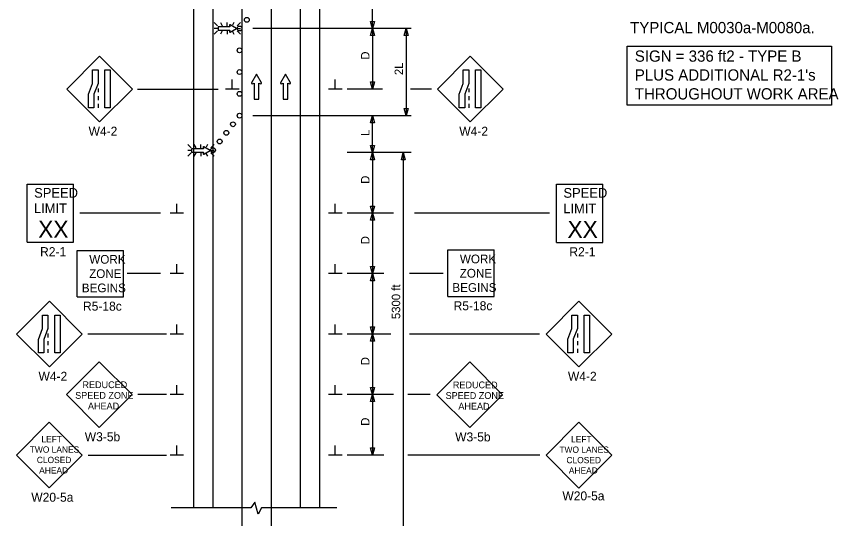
# Model space of a CAD drawing. Extents: x 16553 to 18478, y 5759 to 7026.
# Drawn here: x 16725 to 17405, y 6259 to 6674 of the extents above; entities that cross this region are included whole.
import ezdxf

# ---------------------------------------------------------------- set-up
doc = ezdxf.new("R2010")
doc.units = 0
for name, color, linetype in [('ALI_LEGAL_EX', 7, 'Continuous'), ('MT_SCRATCH_LEVEL_E', 7, 'Continuous'), ('PAVT_EDGE_EX', 7, 'Continuous'), ('TRAFFIC_SIGNS_PR', 7, 'Continuous'), ('TYPICAL_TEXT_DIMEN_EX', 7, 'Continuous'), ('TYPICAL_TEXT_DIMEN_PR', 7, 'Continuous')]:
    doc.layers.add(name, color=color, linetype=linetype)

msp = doc.modelspace()

# ---------------------------------------------------------------- linework, layer by layer
at = {"layer": 'ALI_LEGAL_EX'}
for p, q in [((16911.66, 7026.35), (16911.66, 6197.16)), ((16935.66, 7026.35), (16935.66, 6197.16)), ((16935.66, 7026.35), (16935.66, 6197.16))]:
    msp.add_line(p, q, dxfattribs=at)
for points in [[(16911.66, 6626.35), (16911.66, 6601.35)], [(16935.66, 6626.35), (16935.66, 6601.35)], [(16911.66, 6526.35), (16911.66, 6501.35)], [(16935.66, 6526.35), (16935.66, 6501.35)], [(16911.66, 6426.35), (16911.66, 6401.35)], [(16935.66, 6426.35), (16935.66, 6401.35)], [(16911.66, 6326.35), (16911.66, 6301.35)], [(16935.66, 6326.35), (16935.66, 6301.35)]]:
    msp.add_lwpolyline(points, dxfattribs=at)
at = {"layer": 'MT_SCRATCH_LEVEL_E'}
for p, q in [((16923.57, 6625.97), (16919.46, 6618.73)), ((16927.71, 6618.73), (16923.57, 6625.97)), ((16947.62, 6625.97), (16943.51, 6618.73)), ((16951.77, 6618.73), (16947.62, 6625.97)), ((16919.94, 6618.04), (16921.72, 6618.36)), ((16921.72, 6618.36), (16921.72, 6605.1)), ((16925.46, 6605.1), (16925.46, 6618.36)), ((16925.46, 6618.36), (16927.23, 6618.04)), ((16943.99, 6618.04), (16945.77, 6618.36)), ((16945.77, 6618.36), (16945.77, 6605.1)), ((16949.51, 6605.1), (16949.51, 6618.36)), ((16949.51, 6618.36), (16951.29, 6618.04)), ((16921.72, 6605.1), (16925.46, 6605.1)), ((16945.77, 6605.1), (16949.51, 6605.1))]:
    msp.add_line(p, q, dxfattribs=at)
for centre, start, end in [((16919.86, 6618.5), 150.42484, 279.96381), ((16927.3, 6618.5), 260.03619, 29.77312), ((16943.92, 6618.5), 150.42484, 279.96381), ((16951.36, 6618.5), 260.03619, 29.77312)]:
    msp.add_arc(centre, 0.463, start, end, dxfattribs=at)
at = {"layer": 'PAVT_EDGE_EX'}
for p, q in [((16871.66, 6926.66), (16871.66, 6267.34)), ((16887.66, 6926.66), (16887.66, 6267.34)), ((16959.66, 6926.66), (16959.66, 6267.34)), ((16975.66, 6926.66), (16975.66, 6267.34))]:
    msp.add_line(p, q, dxfattribs=at)
at = {"layer": 'TRAFFIC_SIGNS_PR'}
for p, q in [((16891.44, 6665.74), (16888.62, 6668.56)), ((16893.74, 6668.56), (16895.36, 6665.74)), ((16899.52, 6665.74), (16899.52, 6668.56)), ((16904.99, 6668.56), (16903.79, 6666.46)), ((16910.43, 6668.55), (16907.61, 6665.74)), ((16891.44, 6663.7), (16888.62, 6663.7)), ((16891.44, 6661.67), (16888.62, 6658.85)), ((16895.39, 6661.67), (16893.76, 6658.85)), ((16899.52, 6661.67), (16899.52, 6658.85)), ((16903.71, 6661.04), (16904.97, 6658.85)), ((16907.61, 6663.7), (16910.43, 6663.7)), ((16910.43, 6658.85), (16907.61, 6661.67)), ((16793.8, 6640.77), (16766.64, 6613.62)), ((16820.95, 6613.62), (16793.8, 6640.77)), ((17100.48, 6640.77), (17073.32, 6613.62)), ((17127.63, 6613.62), (17100.48, 6640.77)), ((16766.64, 6613.62), (16793.8, 6586.47)), ((16792.55, 6614.11), (16792.55, 6610.91)), ((16793.8, 6586.47), (16820.95, 6613.62)), ((17073.32, 6613.62), (17100.48, 6586.46)), ((17099.23, 6614.11), (17099.23, 6610.91)), ((17100.48, 6586.46), (17127.63, 6613.62)), ((16792.55, 6607.71), (16792.55, 6604.51)), ((17099.23, 6607.71), (17099.23, 6604.51)), ((16792.55, 6601.31), (16792.55, 6598.11)), ((17099.23, 6601.31), (17099.23, 6598.11)), ((16869.6, 6564.95), (16866.78, 6567.77)), ((16871.9, 6567.77), (16873.52, 6564.95)), ((16877.68, 6564.95), (16877.68, 6567.77)), ((16883.15, 6567.77), (16881.94, 6565.68)), ((16888.59, 6567.77), (16885.77, 6564.95)), ((16869.6, 6562.92), (16866.78, 6562.92)), ((16869.6, 6560.88), (16866.78, 6558.06)), ((16873.55, 6560.88), (16871.92, 6558.06)), ((16877.68, 6560.88), (16877.68, 6558.06)), ((16881.87, 6560.25), (16883.13, 6558.06)), ((16885.77, 6562.92), (16888.59, 6562.92)), ((16888.59, 6558.07), (16885.77, 6560.88)), ((16733.92, 6534.98), (16772.37, 6534.98)), ((16733.92, 6486.92), (16733.92, 6534.98)), ((16772.37, 6486.92), (16772.37, 6534.98)), ((17171.81, 6534.92), (17210.26, 6534.92)), ((17171.81, 6486.86), (17171.81, 6534.92)), ((17210.26, 6486.86), (17210.26, 6534.92)), ((16733.92, 6486.92), (16772.37, 6486.92)), ((17171.81, 6486.86), (17210.26, 6486.86)), ((16775.32, 6441.85), (16775.32, 6480.25)), ((16775.32, 6480.25), (16813.72, 6480.25)), ((16813.72, 6441.85), (16813.72, 6480.25)), ((17081.91, 6442.19), (17081.91, 6480.59)), ((17081.91, 6480.59), (17120.31, 6480.59)), ((17120.31, 6442.19), (17120.31, 6480.59)), ((16775.32, 6441.85), (16813.72, 6441.85)), ((17081.91, 6442.19), (17120.31, 6442.19)), ((16752.35, 6438.19), (16725.19, 6411.04)), ((16779.5, 6411.04), (16752.35, 6438.19)), ((17190.35, 6438.22), (17163.2, 6411.06)), ((17217.51, 6411.06), (17190.35, 6438.22)), ((16725.19, 6411.04), (16752.35, 6383.89)), ((16751.1, 6411.53), (16751.1, 6408.33)), ((16752.35, 6383.89), (16779.5, 6411.04)), ((17163.2, 6411.06), (17190.35, 6383.91)), ((17189.11, 6411.55), (17189.11, 6408.35)), ((17190.35, 6383.91), (17217.51, 6411.06)), ((16751.1, 6405.13), (16751.1, 6401.93)), ((17189.11, 6405.15), (17189.11, 6401.95)), ((16751.1, 6398.73), (16751.1, 6395.53)), ((17189.11, 6398.75), (17189.11, 6395.55)), ((16793.62, 6388.23), (16766.47, 6361.08)), ((16820.78, 6361.08), (16793.62, 6388.23)), ((17100.06, 6388.12), (17072.91, 6360.97)), ((17127.21, 6360.97), (17100.06, 6388.12)), ((16766.47, 6361.08), (16793.62, 6333.93)), ((16793.62, 6333.93), (16820.78, 6361.08)), ((17072.91, 6360.97), (17100.06, 6333.81)), ((17100.06, 6333.81), (17127.21, 6360.97)), ((16752.21, 6338.25), (16725.06, 6311.09)), ((16779.37, 6311.09), (16752.21, 6338.25)), ((17190.37, 6338.15), (17163.22, 6310.99)), ((17217.52, 6310.99), (17190.37, 6338.15)), ((16725.06, 6311.09), (16752.21, 6283.94)), ((16752.21, 6283.94), (16779.37, 6311.09)), ((17163.22, 6310.99), (17190.37, 6283.84)), ((17190.37, 6283.84), (17217.52, 6310.99))]:
    msp.add_line(p, q, dxfattribs=at)
for points in [[(16901.35, 6666.39), (16901.58, 6665.09), (16891.86, 6665.09), (16891.86, 6662.35), (16901.58, 6662.35), (16901.35, 6661.04)], [(16901.85, 6660.69), (16907.16, 6663.7), (16901.85, 6666.74)], [(16879.51, 6565.6), (16879.74, 6564.3), (16870.02, 6564.3), (16870.02, 6561.56), (16879.74, 6561.56), (16879.51, 6560.26)], [(16880.01, 6559.9), (16885.32, 6562.92), (16880.01, 6565.96)]]:
    msp.add_lwpolyline(points, dxfattribs=at)
for points in [[(16792.55, 6629.36), (16792.55, 6618.18), (16789.2, 6609.29), (16789.2, 6598.11), (16784.71, 6598.11), (16784.71, 6609.29), (16788.05, 6618.18), (16788.05, 6629.36)], [(16802.68, 6629.36), (16802.68, 6598.11), (16798.19, 6598.11), (16798.19, 6629.36)], [(17099.23, 6629.35), (17099.23, 6618.17), (17095.88, 6609.29), (17095.88, 6598.11), (17091.39, 6598.11), (17091.39, 6609.29), (17094.73, 6618.17), (17094.73, 6629.35)], [(17109.36, 6629.35), (17109.36, 6598.11), (17104.87, 6598.11), (17104.87, 6629.35)], [(16751.1, 6426.78), (16751.1, 6415.6), (16747.76, 6406.71), (16747.76, 6395.53), (16743.26, 6395.53), (16743.26, 6406.71), (16746.61, 6415.6), (16746.61, 6426.78)], [(16761.24, 6426.78), (16761.24, 6395.53), (16756.74, 6395.53), (16756.74, 6426.78)], [(17189.11, 6426.8), (17189.11, 6415.62), (17185.76, 6406.74), (17185.76, 6395.55), (17181.27, 6395.55), (17181.27, 6406.74), (17184.61, 6415.62), (17184.61, 6426.8)], [(17199.24, 6426.8), (17199.24, 6395.55), (17194.75, 6395.55), (17194.75, 6426.8)]]:
    msp.add_lwpolyline(points, close=True, dxfattribs=at)
for centre in [(16915.66, 6670.77), (16909.66, 6663.63), (16909.66, 6645.63), (16909.66, 6627.63), (16909.66, 6609.63), (16909.66, 6591.63), (16904.17, 6584.5), (16898.67, 6577.37), (16893.17, 6570.24), (16887.67, 6563.12)]:
    msp.add_circle(centre, 2, dxfattribs=at)
for centre, start, end in [((16901.69, 6666.44), 61.48329, 189.95933), ((16901.69, 6660.99), 170.73078, 298.89165), ((16879.85, 6565.66), 61.48329, 189.95933), ((16879.85, 6560.2), 170.73078, 298.89165)]:
    msp.add_arc(centre, 0.341, start, end, dxfattribs=at)
at = {"layer": 'TYPICAL_TEXT_DIMEN_EX'}
msp.add_lwpolyline([(17230.4, 6649.17), (17399.41, 6649.17), (17399.41, 6600.34), (17230.4, 6600.34)], close=True, dxfattribs=at)
at = {"layer": 'TYPICAL_TEXT_DIMEN_PR'}
for p, q in [((17019.66, 6663.63), (17019.66, 6694.2)), ((17019.66, 6663.63), (17018.09, 6669.49)), ((17018.09, 6669.49), (17019.66, 6669.49)), ((17019.66, 6669.49), (17021.23, 6669.49)), ((17021.23, 6669.49), (17019.66, 6663.63)), ((17051.71, 6663.63), (16920.56, 6663.63)), ((17018.09, 6657.77), (17019.66, 6663.63)), ((17019.66, 6663.63), (17019.66, 6613.63)), ((17019.66, 6663.63), (17021.23, 6657.77)), ((17045.9, 6657.77), (17047.47, 6663.63)), ((17047.47, 6663.63), (17049.04, 6657.77)), ((17047.47, 6663.63), (17047.47, 6591.63)), ((17019.66, 6657.77), (17018.09, 6657.77)), ((17021.23, 6657.77), (17019.66, 6657.77)), ((17047.47, 6657.77), (17045.9, 6657.77)), ((17049.04, 6657.77), (17047.47, 6657.77)), ((16903.59, 6613.63), (16903.59, 6621.42)), ((16988.79, 6613.63), (16988.79, 6621.42)), ((17019.66, 6613.63), (17018.09, 6619.49)), ((17018.09, 6619.49), (17019.66, 6619.49)), ((17019.66, 6619.49), (17021.23, 6619.49)), ((17021.23, 6619.49), (17019.66, 6613.63)), ((17047.47, 6618.5), (17047.47, 6614.73)), ((16825.22, 6613.63), (16891.86, 6613.63)), ((16909.22, 6613.63), (16897.97, 6613.63)), ((16994.41, 6613.63), (16983.16, 6613.63)), ((17027.77, 6613.63), (16998.66, 6613.63)), ((17068.46, 6613.63), (17051.1, 6613.63)), ((17047.47, 6591.63), (17045.9, 6597.49)), ((17045.9, 6597.49), (17047.47, 6597.49)), ((17047.47, 6597.49), (17049.04, 6597.49)), ((17049.04, 6597.49), (17047.47, 6591.63)), ((16920.56, 6591.63), (17051.71, 6591.63)), ((17018.09, 6585.77), (17019.66, 6591.63)), ((17019.66, 6561.07), (17019.66, 6591.63)), ((17019.66, 6591.63), (17021.23, 6585.77)), ((17019.66, 6585.77), (17018.09, 6585.77)), ((17021.23, 6585.77), (17019.66, 6585.77)), ((17019.66, 6561.07), (17018.09, 6566.93)), ((17018.09, 6566.93), (17019.66, 6566.93)), ((17019.66, 6566.93), (17021.23, 6566.93)), ((17021.23, 6566.93), (17019.66, 6561.07)), ((17051.71, 6561.07), (16998.66, 6561.07)), ((17018.09, 6555.21), (17019.66, 6561.07)), ((17019.66, 6561.07), (17019.66, 6511.07)), ((17019.66, 6561.07), (17021.23, 6555.21)), ((17043.53, 6555.21), (17045.1, 6561.07)), ((17045.1, 6561.07), (17045.1, 6209.23)), ((17045.1, 6561.07), (17046.67, 6555.21)), ((17019.66, 6555.21), (17018.09, 6555.21)), ((17021.23, 6555.21), (17019.66, 6555.21)), ((17045.1, 6555.21), (17043.53, 6555.21)), ((17046.67, 6555.21), (17045.1, 6555.21)), ((16857.78, 6511.07), (16857.78, 6518.85)), ((16988.79, 6511.07), (16988.79, 6518.85)), ((17019.66, 6511.07), (17018.09, 6516.93)), ((17018.09, 6516.93), (17019.66, 6516.93)), ((17019.66, 6516.93), (17021.23, 6516.93)), ((17021.23, 6516.93), (17019.66, 6511.07)), ((16844.35, 6511.07), (16777.47, 6511.07)), ((16863.4, 6511.07), (16852.15, 6511.07)), ((16994.41, 6511.07), (16983.16, 6511.07)), ((17036.87, 6511.07), (16998.66, 6511.07)), ((17018.09, 6505.21), (17019.66, 6511.07)), ((17019.66, 6511.07), (17019.66, 6461.07)), ((17019.66, 6511.07), (17021.23, 6505.21)), ((17166.12, 6511.07), (17054.27, 6511.07)), ((17019.66, 6505.21), (17018.09, 6505.21)), ((17021.23, 6505.21), (17019.66, 6505.21)), ((16857.78, 6461.07), (16857.78, 6468.85)), ((16988.79, 6461.07), (16988.79, 6468.85)), ((17019.66, 6461.07), (17018.09, 6466.93)), ((17018.09, 6466.93), (17019.66, 6466.93)), ((17019.66, 6466.93), (17021.23, 6466.93)), ((17021.23, 6466.93), (17019.66, 6461.07)), ((16844.35, 6461.07), (16816.63, 6461.07)), ((16863.4, 6461.07), (16852.15, 6461.07)), ((16994.41, 6461.07), (16983.16, 6461.07)), ((17029.05, 6461.07), (16998.66, 6461.07)), ((17018.09, 6455.21), (17019.66, 6461.07)), ((17019.66, 6455.21), (17018.09, 6455.21)), ((17019.66, 6461.07), (17019.66, 6411.07)), ((17019.66, 6461.07), (17021.23, 6455.21)), ((17021.23, 6455.21), (17019.66, 6455.21)), ((17078.13, 6461.07), (17050.16, 6461.07)), ((16857.78, 6411.07), (16857.78, 6418.85)), ((16988.79, 6411.07), (16988.79, 6418.85)), ((17019.66, 6411.07), (17018.09, 6416.93)), ((17018.09, 6416.93), (17019.66, 6416.93)), ((17019.66, 6416.93), (17021.23, 6416.93)), ((17021.23, 6416.93), (17019.66, 6411.07)), ((16849.11, 6411.07), (16784, 6411.07)), ((16863.4, 6411.07), (16852.15, 6411.07)), ((16994.41, 6411.07), (16983.16, 6411.07)), ((17034.88, 6411.07), (16998.66, 6411.07)), ((17018.09, 6405.21), (17019.66, 6411.07)), ((17019.66, 6411.07), (17019.66, 6361.07)), ((17019.66, 6411.07), (17021.23, 6405.21)), ((17157.84, 6411.07), (17050.1, 6411.07)), ((17019.66, 6405.21), (17018.09, 6405.21)), ((17021.23, 6405.21), (17019.66, 6405.21)), ((16857.78, 6361.07), (16857.78, 6368.85)), ((16988.79, 6361.07), (16988.79, 6368.85)), ((17019.66, 6361.07), (17018.09, 6366.93)), ((17018.09, 6366.93), (17019.66, 6366.93)), ((17019.66, 6366.93), (17021.23, 6366.93)), ((17021.23, 6366.93), (17019.66, 6361.07)), ((16849.28, 6361.07), (16825.55, 6361.07)), ((16863.4, 6361.07), (16852.15, 6361.07)), ((16994.41, 6361.07), (16983.16, 6361.07)), ((17036.87, 6361.07), (16998.66, 6361.07)), ((17018.09, 6355.21), (17019.66, 6361.07)), ((17019.66, 6361.07), (17019.66, 6311.07)), ((17019.66, 6361.07), (17021.23, 6355.21)), ((17067.37, 6361.07), (17048.84, 6361.07)), ((17019.66, 6355.21), (17018.09, 6355.21)), ((17021.23, 6355.21), (17019.66, 6355.21)), ((16857.78, 6311.07), (16857.78, 6318.85)), ((16988.79, 6311.07), (16988.79, 6318.85)), ((17019.66, 6311.07), (17018.09, 6316.93)), ((17018.09, 6316.93), (17019.66, 6316.93)), ((17019.66, 6316.93), (17021.23, 6316.93)), ((17021.23, 6316.93), (17019.66, 6311.07)), ((16784.27, 6311.07), (16849.28, 6311.07)), ((16863.4, 6311.07), (16852.15, 6311.07)), ((16994.41, 6311.07), (16983.16, 6311.07)), ((17029.05, 6311.07), (16998.66, 6311.07)), ((17157.97, 6311.07), (17048.84, 6311.07)), ((16922.27, 6272.14), (16919.01, 6267.34)), ((16925.01, 6262.2), (16922.27, 6272.14)), ((16919.01, 6267.34), (16853.07, 6267.34)), ((16927.75, 6267.34), (16925.01, 6262.2)), ((16990.08, 6267.34), (16927.75, 6267.34))]:
    msp.add_line(p, q, dxfattribs=at)

# ---------------------------------------------------------------- texts
at = {"layer": 'TRAFFIC_SIGNS_PR'}
for s, height, p in [('W4-2', 7.44, (16784.75, 6575.03)), ('W4-2', 7.44, (17091.43, 6575.02)), ('SPEED', 8.01, (16739.7, 6523.82)), ('SPEED', 8.01, (17177.59, 6523.76)), ('LIMIT', 8.01, (16739.54, 6511.01)), ('LIMIT', 8.01, (17177.43, 6510.95)), ('XX', 14.048, (16743.05, 6490.68)), ('XX', 14.048, (17180.94, 6490.62)), ('R2-1', 7.449, (16744.61, 6475.46)), ('R2-1', 7.449, (17182.5, 6475.4)), ('WORK', 7.217, (16785.32, 6469.22)), ('WORK', 7.217, (17091.91, 6469.55)), ('ZONE', 7.217, (16785.2, 6457.41)), ('ZONE', 7.217, (17091.79, 6457.74)), ('BEGINS', 7.217, (16779.13, 6445.6)), ('BEGINS', 7.217, (17085.72, 6445.94)), ('R5-18c', 7.44, (16780.13, 6430.41)), ('R5-18c', 7.44, (17086.72, 6430.75)), ('W4-2', 7.44, (16743.31, 6372.45)), ('W4-2', 7.44, (17181.31, 6372.47)), ('REDUCED', 5.6, (16779.68, 6366.39)), ('REDUCED', 5.6, (17086.12, 6366.27)), ('SPEED ZONE', 5.6, (16773.67, 6357.59)), ('SPEED ZONE', 5.6, (17080.11, 6357.47)), ('AHEAD', 5.6, (16784.23, 6348.79)), ('AHEAD', 5.6, (17090.67, 6348.67)), ('LEFT', 5.2, (16745.75, 6321.63)), ('W3-5b', 7.44, (16781.58, 6322.49)), ('W3-5b', 7.44, (17088.01, 6322.37)), ('LEFT', 5.2, (17183.91, 6321.53)), ('TWO LANES', 5.2, (16736.07, 6313.03)), ('TWO LANES', 5.2, (17174.23, 6312.93)), ('CLOSED', 5.2, (16741.92, 6304.43)), ('CLOSED', 5.2, (17180.09, 6304.33)), ('AHEAD', 5.2, (16743.87, 6295.83)), ('AHEAD', 5.2, (17182.03, 6295.73)), ('W20-5a', 7.44, (16737.35, 6272.5)), ('W20-5a', 7.44, (17176.72, 6273.63))]:
    msp.add_text(s, height=height, dxfattribs=at).set_placement(p)
at = {"layer": 'TYPICAL_TEXT_DIMEN_EX'}
for s, p in [('TYPICAL M0030a-M0080a.', (17232.73, 6659.75)), ('SIGN = 336 ft2 - TYPE B', (17236.63, 6636.19)), ("PLUS ADDITIONAL R2-1's", (17236.63, 6620.59)), ('THROUGHOUT WORK AREA', (17236.63, 6604.99))]:
    msp.add_text(s, height=9.3, dxfattribs=at).set_placement(p)
at = {"layer": 'TYPICAL_TEXT_DIMEN_PR'}
for s, p in [('D', (17017.1, 6637.85)), ('2L', (17044.91, 6625.14)), ('L', (17017.1, 6574.93)), ('D', (17017.11, 6535.29)), ('D', (17017.11, 6485.29)), ('5300 ft', (17042.55, 6423.43)), ('D', (17017.11, 6385.29)), ('D', (17017.11, 6335.29))]:
    msp.add_text(s, height=7, rotation=90, dxfattribs=at).set_placement(p)

doc.saveas('drawing.dxf')
